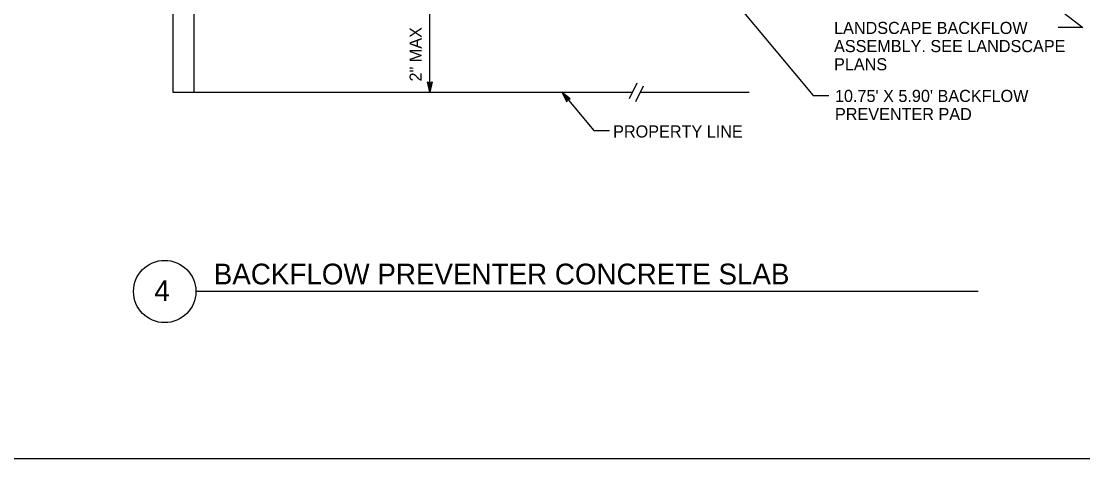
# Model space of a CAD drawing. Extents: x -1680 to 1155, y -802 to 799.
# Drawn here: x 20 to 633, y -802 to -549 of the extents above; entities that cross this region are included whole.
import ezdxf

# ---------------------------------------------------------------- set-up
doc = ezdxf.new("R2010")
doc.units = 0
doc.layers.add('G-TTLB-VIEW', color=7, linetype='Continuous')
doc.layers.add('Misc CnstDet(22)', color=7, linetype='Continuous')

msp = doc.modelspace()

# ---------------------------------------------------------------- linework, layer by layer
at = {"layer": 'G-TTLB-VIEW'}
msp.add_lwpolyline([(-548.79, 598.03), (1053.55, 598.03), (1053.55, -801.99), (-548.79, -801.99)], close=True, dxfattribs=at)
at = {"layer": 'Misc CnstDet(22)'}
for p, q in [((119.59, -496.61), (119.59, -590.18)), ((107.55, -496.97), (107.55, -590.18)), ((256.01, -590.18), (256.01, -538.09)), ((256.01, -590.18), (254.68, -584.18)), ((254.68, -584.18), (254.68, -584.18)), ((254.68, -584.18), (256.01, -584.98)), ((256.01, -588.79), (255.04, -584.41)), ((256.01, -587.42), (255.38, -584.59)), ((256.01, -586.03), (255.74, -584.83)), ((256.01, -584.98), (257.35, -584.18)), ((257.35, -584.18), (256.01, -590.18)), ((256.99, -584.39), (256.01, -588.8)), ((256.63, -584.63), (256.01, -587.42)), ((256.29, -584.8), (256.01, -586.03)), ((257.35, -584.18), (257.35, -584.18)), ((375.47, -584.89), (371.09, -593.88)), ((379.13, -586.68), (374.75, -595.67)), ((107.55, -590.18), (372.89, -590.18)), ((256.01, -590.18), (256.01, -590.18)), ((337.06, -593.92), (332.18, -590.18)), ((332.18, -590.18), (332.18, -590.18)), ((332.18, -590.18), (335.01, -595.63)), ((336.64, -593.98), (333.06, -591.24)), ((333.07, -591.25), (335.13, -595.22)), ((336.22, -594.03), (333.95, -592.3)), ((333.95, -592.3), (335.29, -594.86)), ((335.84, -594.12), (334.84, -593.35)), ((334.84, -593.35), (335.41, -594.45)), ((335.01, -595.63), (335.51, -594.17)), ((335.51, -594.17), (337.06, -593.92)), ((337.06, -593.92), (337.06, -593.92)), ((377.42, -590.18), (440.45, -590.18)), ((335.01, -595.63), (335.01, -595.63)), ((572.66, -705.3), (120.77, -705.3))]:
    msp.add_line(p, q, dxfattribs=at)
for points in [[(488.46, -441.29), (633.13, -552.69), (618.88, -552.69)], [(432.27, -538.09), (477.44, -592.04), (486.56, -592.04)], [(332.18, -590.18), (350.64, -612.23), (359.76, -612.23)]]:
    msp.add_lwpolyline(points, dxfattribs=at)
msp.add_circle((102.77, -705.3), 18, dxfattribs=at)

# ---------------------------------------------------------------- texts
for s, rotation, p in [('LANDSCAPE BACKFLOW', 360, (489.47, -556.45)), ('2" MAX', 90, (251.23, -583.91)), ('ASSEMBLY. SEE LANDSCAPE ', 360, (489.47, -566.95)), ('PLANS', 360, (489.47, -577.45))]:
    msp.add_text(s, height=7, rotation=rotation, dxfattribs=at).set_placement(p)
for s, height, p in [("10.75' X 5.90' BACKFLOW", 7, (490, -595.76)), ('PREVENTER PAD', 7, (490, -606.26)), ('PROPERTY LINE', 7, (361.85, -616.3)), ('BACKFLOW PREVENTER CONCRETE SLAB', 12, (131.13, -701.2)), ('4', 12, (96.79, -710.82))]:
    msp.add_text(s, height=height, dxfattribs=at).set_placement(p)

doc.saveas('drawing.dxf')
